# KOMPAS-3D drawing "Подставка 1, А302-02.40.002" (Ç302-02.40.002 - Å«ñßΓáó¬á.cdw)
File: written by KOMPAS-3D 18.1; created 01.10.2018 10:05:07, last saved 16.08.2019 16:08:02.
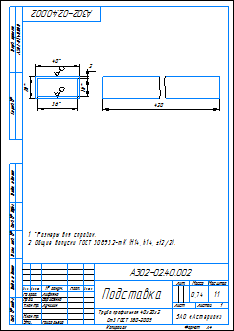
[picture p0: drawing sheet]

Sheet 1: A4, portrait

Document properties: Автор: Пользователь Windows; Полное имя файла: ..\А302-02.40.002 - Подставка 1.m3d; Масса: 0.739092

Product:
- Part/product: Подставка 1  | designation А302-02.40.002
    Масса: 0.739092
    source file: А302-02.40.002 - Подставка.cdw

Title block, sheet 1: Наименование: Подставка; designation: А302-02.40.002; Масса: 0,74; scale: 1:1; Количество листов документа: 1; organisation: ЗАО «Астерион»; Форматы листов документа: A4; stored path: \\192.168.87.28\Konstructor_doc\Мембранные насосы\Мембранный электропривод\А302-00.00.000 - ASTRA-302 (МЭ200)\3Д ПВХ\А302-01.40.002 - Стяжка.cdw; Разработал: Лифлянд; Проверил: Борисенко; Т. контр.: Лучихин; Утвердил: Григорьева

Views: Вид 1, Спереди, Проекционный вид 2
Referenced files in \\192.168.87.28\Konstructor_doc\Мембранные насосы\Мембранный электропривод\А302-00.00.000 - ASTRA-302 (МЭ200)\3Д ПВХ\Отработка\: Труба профильная 25х25х1,5-2.m3d
Referenced files in D:\Мембранные насосы\Мембранный электропривод\А302-00.00.000 - ASTRA-302 (МЭ200)\3Д ПВХ\: А302-02.40.002 - Подставка 1.m3d
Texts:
  Труба профильная 40х20х2
  Ст3 ГОСТ 380-2005
  Подставка 1
Dimensions and other numbers on the sheet: 420; 40; 20; 36; 16; 2; 1:1; 1; 0,74

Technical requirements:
  *Размеры для справок.
  Общие допуски ГОСТ 30893.2-mK (H14, h14,  t2/2).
